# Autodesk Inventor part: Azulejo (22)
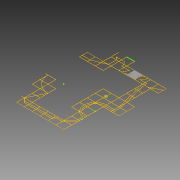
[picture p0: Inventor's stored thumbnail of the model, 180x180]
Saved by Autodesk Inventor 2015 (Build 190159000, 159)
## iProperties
Created: 2015-04
Part Number: Azulejo (22)
Material: Genérico
Document SubType Name: Modeling
Designer: Felipe
Density: 1 g/cm^3
Appearance: Padrão
Author: Felipe
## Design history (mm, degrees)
sketch "Sketch1"
  geometry: L1 (-1510, -7490)-(-1510, -6010); L2 (992.445, 7510)-(992.445, 8990); L3 (1012.445, 7510)-(1012.445, 8990); L4 (-3010, -1490)-(-3010, -10); L5 (-1510, 7490)-(-2990, 7490); L6 (-2990, 10)-(-1510, 10); L7 (-1510, -10)-(-2990, -10); L8 (-1510, -1490)-(-1510, -10); L9 (-10, 9010)-(-10, 10490); L10 (-10, 7510)-(-10, 8990); L11 (-10, 7490)-(-1490, 7490); L12 (-1490, 6010)-(-10, 6010); L13 (-10, 5990)-(-1490, 5990); L14 (-1490, -10)-(-1490, -1490); L15 (-1490, -1490)-(-10, -1490); L16 (-10, -1510)-(-1490, -1510); L17 (-10, -2990)-(-10, -1510); L18 (-10, -5990)-(-10, -4510); L19 (-1490, -7490)-(-10, -7490); L20 (10, 8990)-(10, 7510); L21 (1490, 7510)-(1490, 8990); L22 (10, 6010)-(1490, 6010); L23 (1490, 6010)-(1490, 7490); L24 (1490, 5990)-(10, 5990); L25 (4490, -6010)-(3010, -6010); L26 (10, -1510)-(10, -2990); L27 (10, -3010)-(10, -4490); L28 (10, -4510)-(10, -5990); L29 (10, -5990)-(1490, -5990); L30 (1490, -6010)-(10, -6010); L31 (10, -7490)-(1490, -7490); L32 (2990, 9010)-(2990, 10490); L33 (1510, 8990)-(1510, 7510); L34 (1510, 7510)-(2990, 7510); L35 (2990, 7490)-(1510, 7490); L36 (1510, 7490)-(1510, 6010); L37 (1510, -5990)-(2990, -5990); L38 (2990, -6010)-(1510, -6010); L39 (1510, -7490)-(2990, -7490); L40 (3010, 10490)-(3010, 9010); L41 (3010, 9010)-(4490, 9010); L42 (4490, 8990)-(3010, 8990); L43 (4490, 7490)-(3010, 7490); L44 (4490, 1510)-(4490, 2990); L45 (4490, 10)-(4490, 1490); L46 (4490, -1490)-(4490, -10); L47 (4490, -2990)-(4490, -1510); L48 (3010, -5990)-(4490, -5990); L49 (3010, -7490)-(4490, -7490); L50 (4510, 9010)-(5990, 9010); L51 (5990, 8990)-(4510, 8990); L52 (4510, 7510)-(5990, 7510); L53 (5990, 7490)-(4510, 7490); L54 (4510, 3010)-(5990, 3010); L55 (5990, 2990)-(4510, 2990); L56 (4510, 2990)-(4510, 1510); L57 (4510, 1510)-(5990, 1510); L58 (5990, 1510)-(5990, 1740.185); L59 (5990, 1760.2)-(5990, 2259.8); L60 (5990, 2279.815)-(5990, 2990); L61 (5990, 1490)-(4510, 1490); L62 (4510, 1490)-(4510, 10); L63 (4510, 10)-(5990, 10); L64 (5990, 10)-(5990, 1490)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; A1 r 250 centre (6000, 2010) between (5990, 2259.8) and (5990, 1760.2); A2 r 250 centre (6000, 2010) between (6010, 1760.2) and (6010, 2259.8); A3 r 270 centre (6000, 2010) between (5990, 2279.815) and (5990, 1740.185); A4 r 270 centre (6000, 2010) between (6010, 1740.185) and (6010, 2279.815); A5 r 3010.017 centre (0, 0) between (-1490, -2615.358) and (-346.554, -2990); A6 r 2990.017 centre (0, 0) between (-1490, -2592.316) and (-10, -2990); A7 r 3010.017 centre (0, 0) between (-2603.863, -1510) and (-1510, -2603.863); A8 r 2990.017 centre (0, 0) between (-2580.717, -1510) and (-1510, -2580.717); A9 r 3010.017 centre (0, 0) between (-2990, -346.554) and (-2615.358, -1490); A10 r 2990.017 centre (0, 0) between (-2990, -10) and (-2592.316, -1490); A11 r 2131.367 centre (7500, -1500) between (7490, 631.344) and (6010, 24.017); A12 r 2131.367 centre (7500, -1500) between (5975.983, -10) and (5368.656, -1490); A13 r 2131.367 centre (7500, -1500) between (5368.656, -1510) and (5975.983, -2990); A14 r 2131.367 centre (7500, -1500) between (6010, -3024.017) and (7190, -3608.703); A15 r 1831.367 centre (7500, -1500) between (7490.321, 331.342) and (6463.753, 10); A16 r 1831.367 centre (7500, -1500) between (6435.196, -10) and (6010, -435.196); A17 r 1831.367 centre (7500, -1500) between (5990, -463.753) and (5668.66, -1490); A18 r 1831.367 centre (7500, -1500) between (5668.66, -1510) and (5990, -2536.247); A19 r 1831.367 centre (7500, -1500) between (6010, -2564.804) and (6435.196, -2990); A20 r 1831.367 centre (7500, -1500) between (6463.753, -3010) and (7490, -3331.34); A21 r 2111.367 centre (7500, -1500) between (7490.047, 611.344) and (6024.272, 10); A22 r 2111.367 centre (7500, -1500) between (5990, -24.272) and (5388.656, -1490); A23 r 2111.367 centre (7500, -1500) between (5388.656, -1510) and (5990, -2975.728); A24 r 2111.367 centre (7500, -1500) between (6024.272, -3010) and (7210, -3591.357); A25 r 1811.367 centre (7500, -1500) between (7490.374, 311.342) and (6499.524, 10); A26 r 1811.367 centre (7500, -1500) between (6469.975, -10) and (6010, -469.975); A27 r 1811.367 centre (7500, -1500) between (5990, -499.524) and (5688.66, -1490); A28 r 1811.367 centre (7500, -1500) between (5688.66, -1510) and (5990, -2500.476); A29 r 1811.367 centre (7500, -1500) between (6010, -2530.025) and (6469.975, -2990); A30 r 1811.367 centre (7500, -1500) between (6499.524, -3010) and (7490, -3311.34); A31 r 449.871 centre (7499.449, -4060.672) between (7510, -4510.419) and (7521.546, -4510); 5 further points
  constraints: 1042 end point, 64 point on circle, 31 centre point, 13 point on line, 1 horizontal, 1 other
extrude "Extrusion1" new body sketch "Sketch1" distance "d0" = 60; taper "d1" = 0 deg
extrude "Extrusion2" new body sketch "Sketch1" distance "d2" = 60; taper "d3" = 0 deg
body "Solid1"
body "Solid2"
